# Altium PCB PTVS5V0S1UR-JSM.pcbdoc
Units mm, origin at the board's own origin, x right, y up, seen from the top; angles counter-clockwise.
Board outline 17.03 x 14.56 mm, 2 copper layers (Top Layer, Bottom Layer), stack 0 mm thick; 1 components, 0 nets, 2 pads, 0 vias.
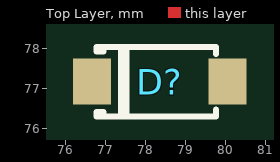
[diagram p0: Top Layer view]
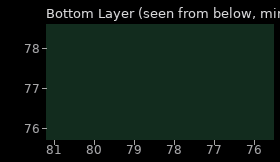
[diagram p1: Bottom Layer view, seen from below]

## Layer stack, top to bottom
Top Layer: signal copper (thickness not stored)
Bottom Layer: signal copper (thickness not stored)

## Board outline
86.885,69.85 69.85,69.85 69.85,84.41 86.885,84.41

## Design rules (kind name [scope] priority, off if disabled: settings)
PasteMaskExpansion "Paste Mask Expansion" [All] p1: expansion=0
SolderMaskExpansion "Solder Mask Expansion" [IsVia] p1: expansion=-25.4 istentingtop=TRUE
SolderMaskExpansion "Solder Mask Expansion" [All] p2: expansion=0.051 istentingtop=FALSE

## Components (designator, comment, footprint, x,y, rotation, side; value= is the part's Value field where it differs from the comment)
D? "PTVS5V0S1UR-JSM" SOD-123_L2.8-W1.8-LS3.7-RD 78.367,77.16 r0 top

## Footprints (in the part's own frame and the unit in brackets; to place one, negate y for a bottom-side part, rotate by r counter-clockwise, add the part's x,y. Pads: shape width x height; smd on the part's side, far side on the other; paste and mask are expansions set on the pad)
SOD-123_L2.8-W1.8-LS3.7-RD [mm]
  rect 0.95x1.15 smd: 1(-1.692,0) 2(1.692,0)
  silkscreen extent -1.58,-0.87 1.41,0.87

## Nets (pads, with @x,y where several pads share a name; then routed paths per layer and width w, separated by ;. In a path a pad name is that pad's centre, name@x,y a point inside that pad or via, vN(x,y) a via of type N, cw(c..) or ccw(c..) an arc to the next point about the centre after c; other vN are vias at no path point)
pads on no net: D?.1 D?.2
